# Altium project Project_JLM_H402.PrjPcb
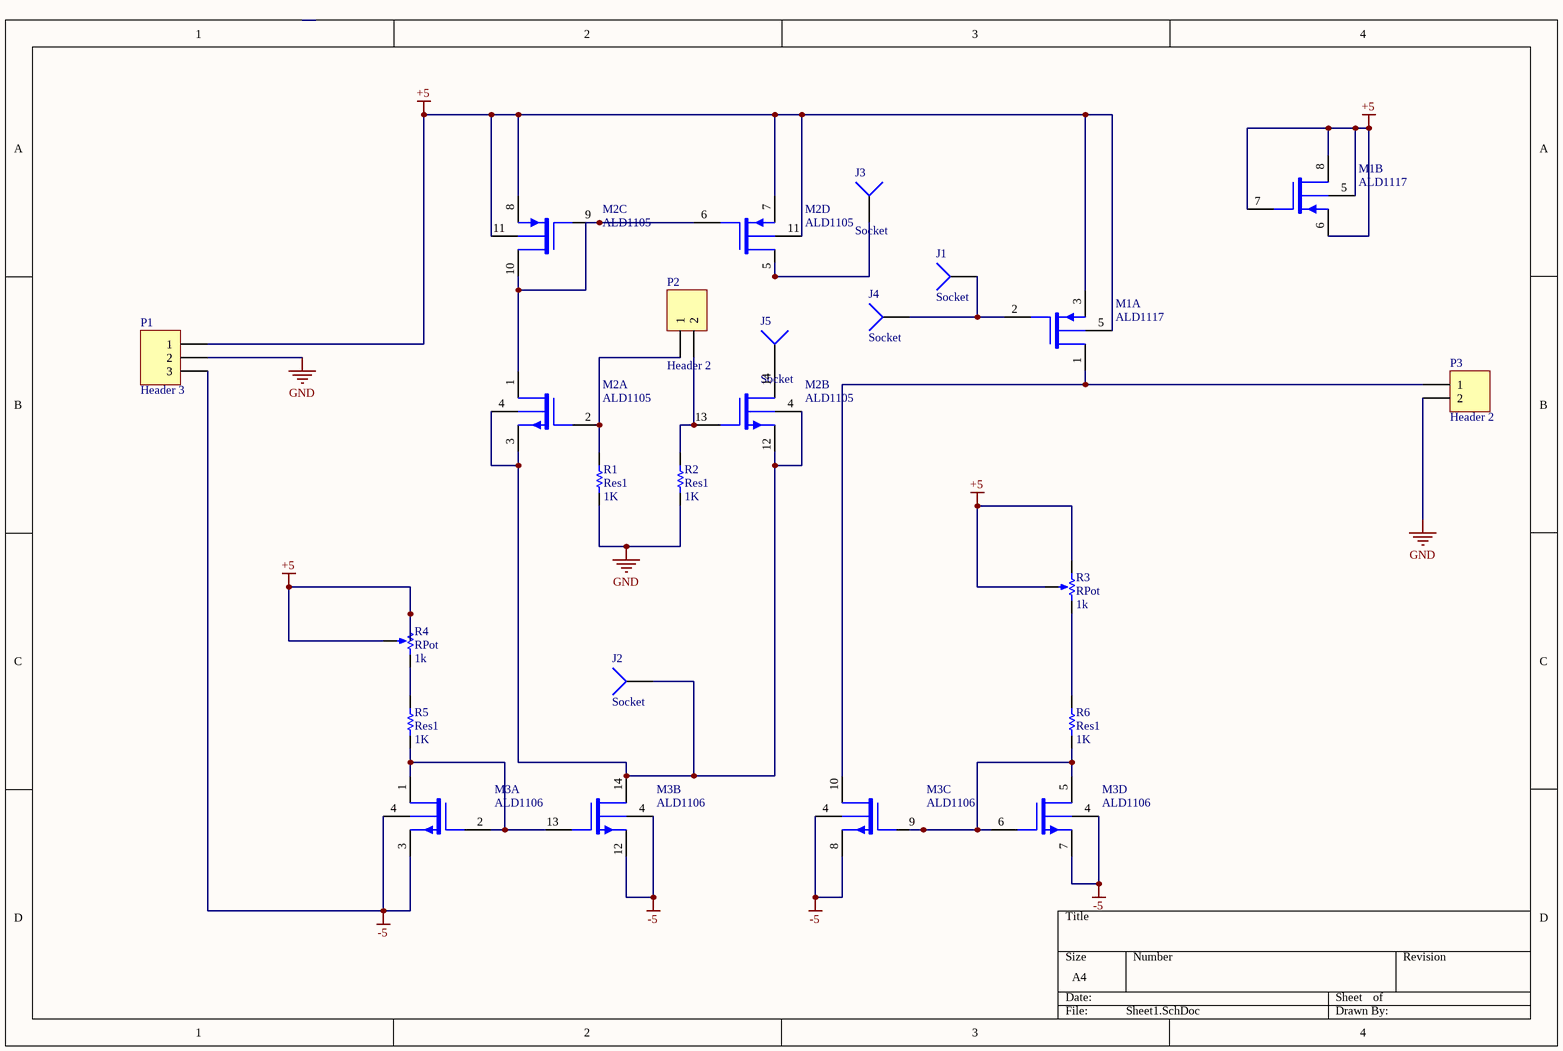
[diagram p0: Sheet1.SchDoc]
1 sheet, 17 parts. Net scope: global (net labels, ports and power ports of the same name join across sheets).
Board file: PCB1.PcbDoc

## Sheet Sheet1.SchDoc
size A4

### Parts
J1  Socket  [PIN1]
J2  Socket  [PIN1]
J3  Socket  [PIN1]
J4  Socket  [PIN1]
J5  Socket  [PIN1]
M1  ALD1117  [DIP-8]  (parts A,B of 2)
M2  ALD1105  [DIP-14]  (parts A,B,C,D of 4)
M3  ALD1106  [DIP-14]  (parts A,B,C,D of 4)
P1  Header 3  [HDR1X3]
P2  Header 2  [HDR1X2]
P3  Header 2  [HDR1X2]
R1  Res1  value 1K  [AXIAL-0.3]
R2  Res1  value 1K  [AXIAL-0.3]
R3  RPot  value 1k  [VR5]
R4  RPot  value 1k  [VR5]
R5  Res1  value 1K  [AXIAL-0.3]
R6  Res1  value 1K  [AXIAL-0.3]

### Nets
+5: M1.3(SP1) M1.5(V+) M1.6(SP2) M1.7(GP2) M1.8(DP2) M2.7(SP1) M2.8(SP2) M2.11(V+) P1.1 R3.1(TOP) R3.2(TAP) R4.1(TOP) R4.2(TAP)
-5: M3.3(SN1) M3.4(V-) M3.7(SN4) M3.8(SN3) M3.12(SN2) P1.3
GND: P1.2 P3.2 R1.1 R2.1
NetJ1_1: J1.1 J4.1 M1.2(GP1)
NetJ2_1: J2.1 M2.3(SN1) M2.4(V-) M2.12(SN2) M3.14(DN2)
NetJ3_1: J3.1 M2.5(DP1)
NetJ5_1: J5.1 M2.14(DN2)
NetM1_1: M1.1(DP1) M3.10(DN3) P3.1
NetM2_1: M2.1(DN1) M2.6(GP1) M2.9(GP2) M2.10(DP2)
NetM2_2: M2.2(GN1) P2.1 R1.2
NetM2_13: M2.13(GN2) P2.2 R2.2
NetM3_1: M3.1(DN1) M3.2(GN1) M3.13(GN2) R5.1
NetM3_5: M3.5(DN4) M3.6(GN4) M3.9(GN3) R6.1
NetR3_3: R3.3(BOT) R6.2
NetR4_3: R4.3(BOT) R5.2

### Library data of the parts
M1 = ALD1117: Dual P-channel matched MOSFET array
M2 = ALD1105: Dual P-channel and dual N-channel matched MOSFET array
M3 = ALD1106: Quad N-channel matched MOSFET array
P1 = Header 3: Header, 3-Pin
P2 P3 = Header 2: Header, 2-Pin
R1 R2 R5 R6 = Res1: Resistor
R3 R4 = RPot: Potentiometer; Sim Note: Enter the Resistance value and the set point into parameter fields.; Set Position: 0.5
